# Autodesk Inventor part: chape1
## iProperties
Created: 2009-03
Part Number: chape1
Document SubType Name: Modeling
Designer: Ordi1
Author: Ordi1
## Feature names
1. Extrusion2
2. Perçage1 [Hole]
3. Chanfrein1 [Chamfer]
4. Perçage2 [Hole]
